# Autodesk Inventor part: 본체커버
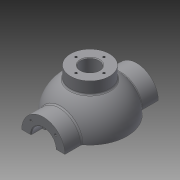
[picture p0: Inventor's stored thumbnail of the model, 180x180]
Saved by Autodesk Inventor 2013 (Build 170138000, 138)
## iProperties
Created: 2015-12
Part Number: 본체커버
Material: 일반
Document SubType Name: Modeling
Designer: mduedu
Density: 2.71 g/cm^3
Mass: 487.453 g
Surface Area: 431.319 cm^2
Volume: 179.872 cm^3
Author: mduedu
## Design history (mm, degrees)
sketch "스케치1"
  geometry: L1 (-53, 0)-(53, 0); A1 r 53 centre (0, 0) between (53, 0) and (-53, 0); 2 further points
  constraints: 2 coincident, 2 end point, 2 point on circle, 1 centre point, 1 horizontal, 1 midpoint
  dimensions: "d0" = 53 radius of A1
revolve "회전1" sketch "스케치1" stored, may be unused: angle "d2" = 90 deg
feature "쉘1" dims "d11" = 8
node "작업 평면1"
sketch "스케치2"
  geometry: C1 r 31 at (0, 0); 1 further point
  constraints: 1 centre point, 1 coincident
  dimensions: "d4" = 62 diameter of C1
extrude "돌출1" join sketch "스케치2" stored distance "d5" = 10; taper "d6" = 0 deg
hole "구멍1" diameter "d14" = 35; stored, may be unused: countersink angle "d18" = 90 deg, drill point angle "d20" = 0 deg; dims "d12" = 10, "d13" = 10, "d15" = 6, "d16" = 4, "d17" = 2, "d19" = 16
hole "구멍2" diameter "d23" = 27; stored, may be unused: countersink angle "d27" = 90 deg, drill point angle "d29" = 0 deg; dims "d21" = 10, "d22" = 10, "d24" = 6, "d25" = 4, "d26" = 2, "d28" = 16
fillet "모깎기1" dims "d30" = 0.3
chamfer "모따기1" distance "d40" = 1; stored, may be unused: second distance "d41" = 2, angle "d42" = 45 deg
sketch "스케치4"
  geometry: L1 (0, 0)-(0, -25); L2 (0, 0)-(-17.678, -17.678); A1 r 25 centre (0, 0) between (-17.678, -17.678) and (0, -25); 1 further point
  constraints: 4 end point, 2 point on circle, 1 centre point, 1 coincident, 1 vertical
  dimensions: "d43" = 50 diameter of A1; "d47" = 45 deg angle of L1 L2
hole "구멍4" sketch "스케치4" at (-17.678, -17.678) diameter "d49" = 3.242; stored, may be unused: countersink angle "d53" = 90 deg, drill point angle "d55" = 118 deg; dims "d50" = 11, "d51" = 4, "d52" = 2, "d54" = 13
node "작업 평면3"
sketch "스케치6"
  geometry: C1 r 65 at (0, 0); 1 further point
  constraints: 1 centre point, 1 coincident
  dimensions: "d78" = 130 diameter of C1
extrude "돌출3" join sketch "스케치6" distance "d80" = 10; taper "d81" = 0 deg
sketch "스케치7"
  geometry: C1 r 20 at (0, 0); 1 further point
  constraints: 1 centre point, 1 coincident
  dimensions: "d82" = 40 diameter of C1
extrude "돌출4" join sketch "스케치7" stored distance "d84" = 10; taper "d85" = 0 deg
sketch "스케치8"
  geometry: 2 further points
  constraints: 1 coincident
hole "구멍6" sketch "스케치8" at (0, 0) diameter "d86" = 20; stored, may be unused: countersink angle "d90" = 90 deg, drill point angle "d92" = 118 deg; dims "d87" = 7, "d88" = 40, "d89" = 5, "d91" = 10
fillet "모깎기2" dims "d93" = 0.3
sketch "스케치9"
  geometry: L1 (65, -75)-(-65, -75) reference; L2 (-45, -75)-(-38.245, -36.692); A1 r 53 centre (0, 0) between (42.988, 31) and (42.988, -31) reference; 1 further point
  constraints: 2 end point, 1 point on circle, 1 point on line
  dimensions: "d94" = 45 horizontal distance of L2.start point (0, 0); "d95" = 80 deg angle of L2 L1
feature "리브1" sketch "스케치9" dims "d96" = 1, "d97" = 8, "d98" = 0, "d99" = 0, "d100" = 1, "d101" = 1
sketch "스케치10"
  geometry: L1 (0, 0)-(0, -55); L2 (0, 0)-(-38.891, -38.891); A1 r 55 centre (0, 0) between (0, -55) and (-38.891, -38.891); 2 further points
  constraints: 4 end point, 2 coincident, 2 point on circle, 1 centre point, 1 vertical
  dimensions: "d105" = 110 diameter of A1; "d107" = 45 deg angle of L1 L2
hole "구멍7" sketch "스케치10" at (-38.891, -38.891) diameter "d109" = 10; stored, may be unused: countersink angle "d113" = 90 deg, drill point angle "d115" = 118 deg; dims "d110" = 7, "d111" = 40, "d112" = 5, "d114" = 10
fillet "모깎기3" dims "d120" = 3
fillet "모깎기4" dims "d121" = 3, "d122" = 3
fillet "모깎기5" dims "d123" = 3
fillet "모깎기6" dims "d124" = 3
sketch "스케치11"
  geometry: C1 r 5 at (-38.891, 38.891) reference; C2 r 5 at (38.891, 38.891) reference; C3 r 5 at (38.891, -38.891) reference; C4 r 5 at (-38.891, -38.891) reference; C5 r 20 at (0, 0) reference; C6 r 65 at (0, 0) reference; 1 further point
  constraints: 3 other
feature "엠보싱1" sketch "스케치11" dims "d125" = 0.5, "d126" = 0
sketch "스케치12"
  geometry: L1 (0, 100)-(0, -100); L2 (0, 100)-(-150, 100); L3 (-150, 100)-(-150, -100); L4 (-150, -100)-(0, -100); 2 further points
  constraints: 8 end point, 3 perpendicular, 1 coincident, 1 midpoint, 1 vertical
  dimensions: "d127" = 200 distance of L2.end L3.end; "d129" = 150 distance of L3.end L1.end
extrude "돌출5" cut sketch "스케치12" stored distance "d130" = 10; taper "d131" = 0 deg
node "작업 평면4"
sketch "스케치16"
  geometry: C1 r 28 at (0, 0); 1 further point
  constraints: 1 centre point, 1 coincident
  dimensions: "d148" = 56 diameter of C1
extrude "돌출9" join sketch "스케치16" stored distance "d150" = 5; taper "d151" = 0 deg
hole "구멍8" diameter "d154" = 26; stored, may be unused: countersink angle "d158" = 90 deg, drill point angle "d160" = 118 deg; dims "d152" = 10, "d153" = 10, "d155" = 6, "d156" = 4, "d157" = 2, "d159" = 8
sketch "스케치17" dims "d161" = 40
  geometry: 3 further points
  constraints: 2 vertical alignment, 1 coincident, 2 other
hole "구멍9" sketch "스케치17" at (0, 20) diameter "d163" = 3.242; stored, may be unused: countersink angle "d167" = 90 deg, drill point angle "d169" = 118 deg; dims "d164" = 8, "d165" = 4, "d166" = 2, "d168" = 10
fillet "모깎기11" dims "d173" = 3
chamfer "모따기2" distance "d174" = 1; stored, may be unused: second distance "d175" = 2, angle "d176" = 45 deg
node "솔리드1"
mirror "대칭1"
mirror "대칭2"
pattern_circular "원형 패턴1" dims angle "d57" = 360 deg
mirror "대칭3"
pattern_circular "원형 패턴3" dims angle "d103" = 360 deg
pattern_circular "원형 패턴4" dims angle "d118" = 360 deg
pattern_circular "원형 패턴5" dims angle "d171" = 360 deg
node "투영된 루프1"
other parameters: "d3" = 67, "d77" = -85, "d147" = 62
